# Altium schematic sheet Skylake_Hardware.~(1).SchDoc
size 431 x 279 mm; Date: Not shown in title block; ApprovedBy: Not shown in title block; CheckedBy: Not shown in title block; Author: Not shown in title block; CompanyName: Not shown in title block; Engineer: Not shown in title block; Organization: Not shown in title block; Address1: Not shown in title block; Address2: Not shown in title block; Address3: Not shown in title block; Address4: Not shown in title block; DocumentNumber: 1; Revision: Use project parameter SCH_Rev; SheetNumber: 8; SheetTotal: 9; PageSetup: Record=PageOptions|CenterHorizontal=True|CenterVertical=True|PrintScale=1.00|XCorrection=1.00|YCorrection=1.00|PrintKind=0|BorderSize=5000000|LeftOffset=0|BottomOffset=0|Orientation=2|PaperLength=1000|PaperWidth=1000|Scale=100|PaperSource=15|PrintQuality=600|MediaType=1|DitherType=10|PaperKind=Letter|PrintScaleMode=1
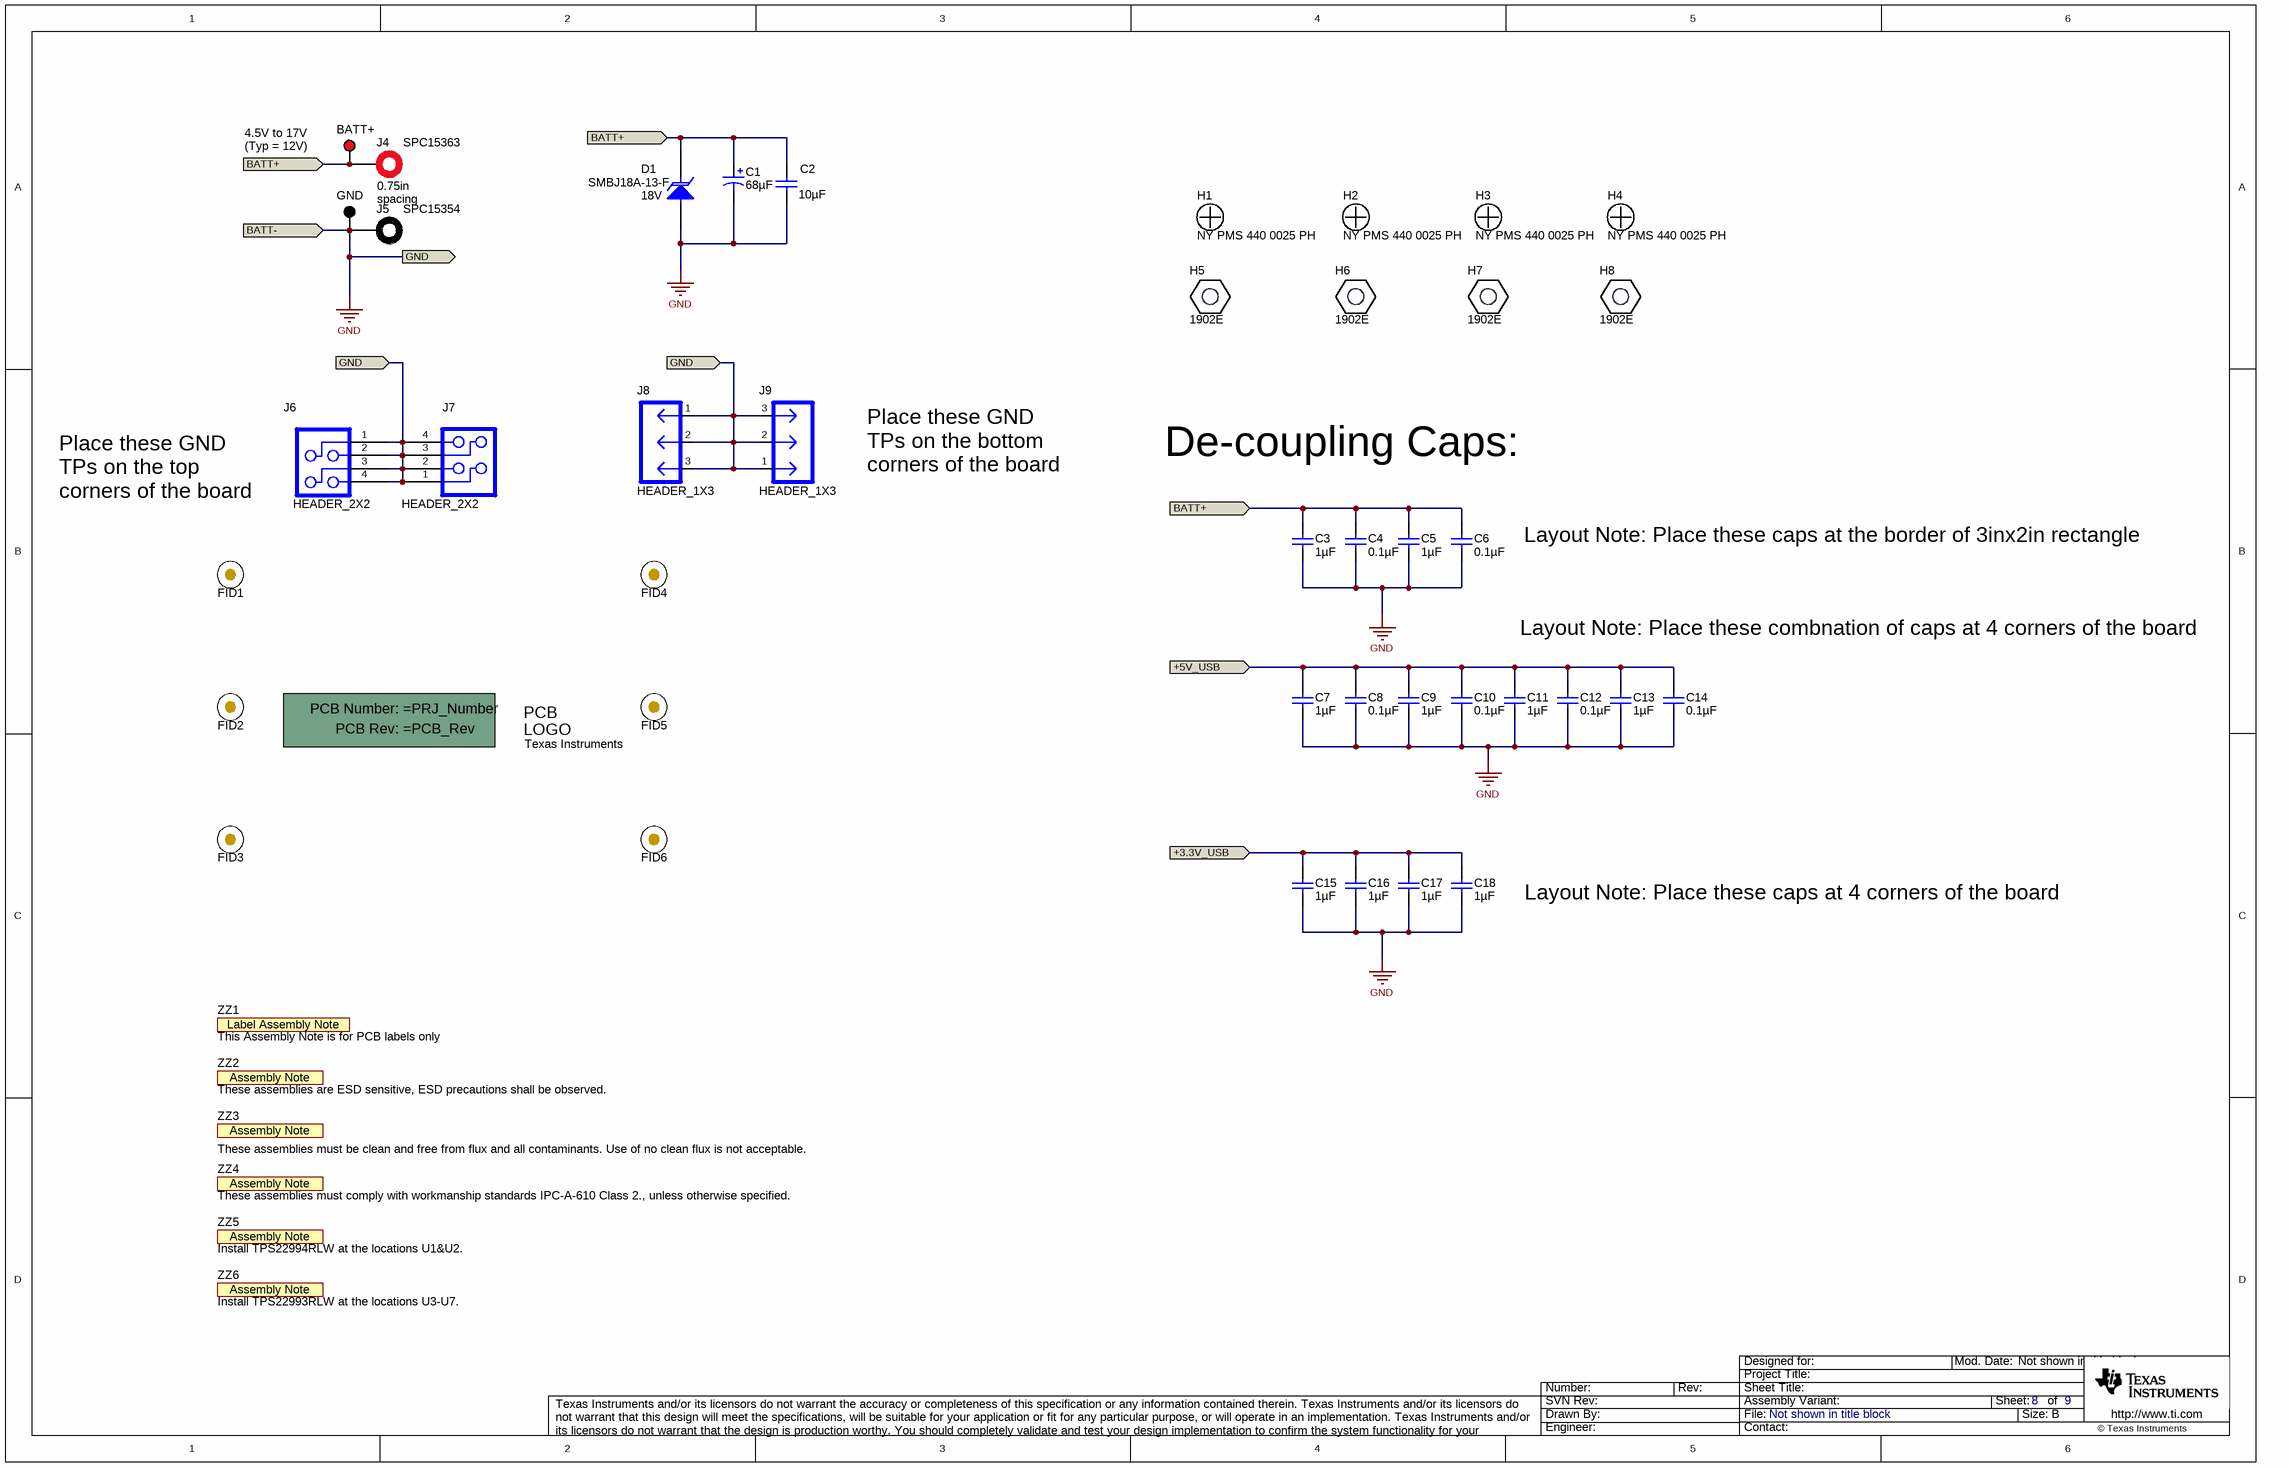
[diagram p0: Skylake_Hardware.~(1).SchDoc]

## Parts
!PCB  Printed Circuit Board  (value not drawn)  (mechanical)
BATT+  5005  [Keystone5005]  (value not drawn)
C1  ValueDisplayed: 68µF  [7361-38]  (hidden comment: TPSV686M035R0150)
C2  ValueDisplayed: 10µF  [1210]  (hidden comment: C3225X6S1V106K250AC)
C3  ValueDisplayed: 1µF  [0805_HV]  (hidden comment: C1608X7R1V105K080AC)
C4  ValueDisplayed: 0.1µF  [0805_HV]  (hidden comment: Taiyo Yuden)
C5  ValueDisplayed: 1µF  [0805_HV]  (hidden comment: C1608X7R1V105K080AC)
C6  ValueDisplayed: 0.1µF  [0805_HV]  (hidden comment: Taiyo Yuden)
C7  ValueDisplayed: 1µF  [0805_HV]  (hidden comment: 0805ZC105KAT2A)
C8  ValueDisplayed: 0.1µF  [0603]  (hidden comment: C0603C104K8RACTU)
C9  ValueDisplayed: 1µF  [0805_HV]  (hidden comment: 0805ZC105KAT2A)
C10  ValueDisplayed: 0.1µF  [0603]  (hidden comment: C0603C104K8RACTU)
C11  ValueDisplayed: 1µF  [0805_HV]  (hidden comment: 0805ZC105KAT2A)
C12  ValueDisplayed: 0.1µF  [0603]  (hidden comment: C0603C104K8RACTU)
C13  ValueDisplayed: 1µF  [0805_HV]  (hidden comment: 0805ZC105KAT2A)
C14  ValueDisplayed: 0.1µF  [0603]  (hidden comment: C0603C104K8RACTU)
C15  ValueDisplayed: 1µF  [0805_HV]  (hidden comment: 0805ZC105KAT2A)
C16  ValueDisplayed: 1µF  [0805_HV]  (hidden comment: 0805ZC105KAT2A)
C17  ValueDisplayed: 1µF  [0805_HV]  (hidden comment: 0805ZC105KAT2A)
C18  ValueDisplayed: 1µF  [0805_HV]  (hidden comment: 0805ZC105KAT2A)
D1  SMBJ18A-13-F  value 18V  [SMB]
FID1  Fiducial  [Fiducial10-20]  (value not drawn)
FID2  Fiducial  [Fiducial10-20]  (value not drawn)
FID3  Fiducial  [Fiducial10-20]  (value not drawn)
FID4  Fiducial  [Fiducial10-20]  (value not drawn)
FID5  Fiducial  [Fiducial10-20]  (value not drawn)
FID6  Fiducial  [Fiducial10-20]  (value not drawn)
GND  5006  [Keystone5006]  (value not drawn)
H1  NY PMS 440 0025 PH  [NY PMS 440 0025 PH]
H2  NY PMS 440 0025 PH  [NY PMS 440 0025 PH]
H3  NY PMS 440 0025 PH  [NY PMS 440 0025 PH]
H4  NY PMS 440 0025 PH  [NY PMS 440 0025 PH]
H5  1902E  [Keystone_1902E]
H6  1902E  [Keystone_1902E]
H7  1902E  [Keystone_1902E]
H8  1902E  [Keystone_1902E]
J4  SPC15363  [Tenma_SPC15363]
J5  SPC15354  [Tenma_SPC15354]
J6  HEADER_2X2  [HDR_2X2]
J7  HEADER_2X2  [HDR_2X2]
J8  HEADER_1X3  [HDR100_1X3]
J9  HEADER_1X3  [HDR100_1X3]
Logo1  Texas Instruments  [TI_Stacked_Overlay_Small]  (no BOM)
ZZ1  This Assembly Note is for PCB labels only  [AssemblyNoteLabel]  (no BOM)
ZZ2  These assemblies are ESD sensitive, ESD precautions shall be observed.  [AssemblyNote]  (no BOM)
ZZ3  These assemblies must be clean and free from flux and all contaminants. Use of no clean flux is not acceptable.  [AssemblyNote]  (no BOM)
ZZ4  These assemblies must comply with workmanship standards IPC-A-610 Class 2., unless otherwise specified.  [AssemblyNote]  (no BOM)
ZZ5  Install TPS22994RLW at the locations U1&U2.  [AssemblyNote]  (no BOM)
ZZ6  Install TPS22993RLW at the locations U3-U7.  [AssemblyNote]  (no BOM)

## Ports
+3.3V_USB (in), +5V_USB (in), BATT+ (in), BATT- (in), GND (in), GND (out)

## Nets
GND: C1.2(-) C2.2 C3.2 C4.2 C5.2 C6.2 C7.2 C8.2 C9.2 C10.2 C11.2 C12.2 C13.2 C14.2 C15.2 C16.2 C17.2 C18.2 D1.2(A) GND.1 J5.1 J6.1 J6.2 J6.3 J6.4 J7.1 J7.2 J7.3 J7.4 J8.1 J8.2 J8.3 J9.1 J9.2 J9.3 ; port BATT-, port GND
+3.3V_USB: C15.1 C16.1 C17.1 C18.1 ; port +3.3V_USB
+5V_USB: C7.1 C8.1 C9.1 C10.1 C11.1 C12.1 C13.1 C14.1 ; port +5V_USB
BATT+: BATT+.1 C1.1(+) C2.1 C3.1 C4.1 C5.1 C6.1 D1.1(K) J4.1 ; port BATT+

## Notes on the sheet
- (near BATT+) 4.5V to 17V
  (Typ = 12V)
- (near J4) 0.75in spacing
- Place these GND TPs on the bottom corners of the board
- De-coupling Caps:
- Place these GND TPs on the top corners of the board
- (near C6) Layout Note: Place these caps at the border of 3inx2in rectangle
- Layout Note: Place these combnation of caps at 4 corners of the board
- (near C18) Layout Note: Place these caps at 4 corners of the board

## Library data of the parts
!PCB = PCB: Manufacturer: Any; SymbolCreator: a0412235
BATT+ = 5005: Test Point, Compact, Red, TH; Manufacturer: Keystone; CompType: Test Point Loop; U/M: EA
C1 = TPSV686M025R0095: CAP, TA, 68uF, 35V, +/-20%, 0.095 ohm, SMD; Manufacturer: AVX; Polarized: Y; CompType: Capacitor; U/M: EA; Cap_F: 0.000068; Tolerance_%: 20; VDC_V: 35; ESR_Ohm: 0.095; IRMS_A: 1.46; TaMin_C: -55; TaMax_C: 125; Cap_Case: V
C2 = GRM32DR61E106KA12L: CAP, CERM, 10uF, 35V, +/-10%, X5R, 1210; Manufacturer: TDK Corporation; Polarized: N; CompType: Capacitor; U/M: EA; Cap_F: 0.00001; Tolerance_%: 10; Value1: Unknown; VDC_V: 35; TaMin_C: -55; TaMax_C: 85
C3 C5 = GRM21BR61E226ME44: CAP, CERM, 1uF, 35V, +/-20%, X5R, 0805; Manufacturer: TDK Corporation; Polarized: N; CompType: Capacitor; U/M: EA; Cap_F: 0.000022; Tolerance_%: 20; Value1: Unknown; VDC_V: 35; TaMin_C: -55; TaMax_C: 85; Cap_Case: 0805
C4 C6 = GRM21BR61E226ME44: CAP, CERM, 0.1uF, 35V, +/-20%, X5R, 0603; Manufacturer: TDK Corporation; Polarized: N; CompType: Capacitor; U/M: EA; Tolerance_%: 20; Value1: Unknown; VDC_V: 35; TaMin_C: -55; TaMax_C: 85; Cap_Case: 0603
C7 C9 C11 C13 C15-C18 = 0805ZC105KAT2A: CAP, CERM, 1uF, 10V, +/-10%, X7R, 0805; Manufacturer: AVX; Polarized: N; CompType: Capacitor; U/M: EA; Cap_F: 0.000001; Tolerance_%: 10; ESR_Ohm: 0.008; Value1: 0.008 ohm; TaMin_C: -55; TaMax_C: 125; Cap_Case: 0805
C8 C10 C12 C14 = GRM188R71C104KA01D: CAP, CERM, 0.1uF, 10V, +/-10%, X7R, 0603; Manufacturer: Kemet; Polarized: N; CompType: Capacitor; U/M: EA; Cap_F: 0.0000001; Tolerance_%: 10; Value1: Unknown; TaMin_C: -55; TaMax_C: 125
D1 = SMBJ18A-13-F: Diode, TVS, Uni, 18V, 600W, SMB; Manufacturer: Diodes Inc.; U/M: EA; Power_W: 5; Vr_V: 18; Value1: 5W
FID1-FID6 = Fiducial: Fiducial mark.  There is nothing to buy or mount.; SymbolCreator: codlsc
GND = 5006: Test Point, Compact, Black, TH; Manufacturer: Keystone; CompType: Test Point Loop; U/M: EA
H1-H4 = NY PMS 440 0025 PH: Machine Screw, Round, #4-40 x 1/4, Nylon, Philips panhead; Manufacturer: B&F Fastener Supply; CompType: Hardware; SymbolCreator: codlsc; U/M: EA
H5-H8 = 1902E: Standoff, Hex, 1"L #4-40 Nylon; Manufacturer: Keystone; SymbolCreator: a0412235; CompType: Hardware
J4 = SPC15363: BANANA JACK, SOLDER LUG, RED, TH; Manufacturer: Tenma; SymbolCreator: a0412235; U/M: EA
J5 = SPC15354: BANANA JACK, SOLDER LUG, BLACK, TH; Manufacturer: Tenma; SymbolCreator: a0412235; U/M: EA
J6 J7 = HEADER_2X2: Header, 2x2-pin, 100mil spacing; Manufacturer: Sullins; PartNumber: PEC02DAAN; area: 40000; Value: PEC02DAAN
J8 J9 = HEADER_1X3: Header, Male 3-pin, 100mil spacing,; Manufacturer: Sullins; PartNumber: PEC03SAAN; area: 30000; Value: PEC03SAAN
Logo1 = TI_Logo: Texas Instrument Corporate Signature; SymbolCreator: codlsc
ZZ1 = AssemblyNoteLabel: SymbolCreator: a0412235
ZZ2-ZZ4 = AssemblyNote: SymbolCreator: codlsc
ZZ5 ZZ6 = AssemblyNote: These assemblies must comply with workmanship standards IPC-A-610 Class 2., unless otherwise specified.; SymbolCreator: codlsc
